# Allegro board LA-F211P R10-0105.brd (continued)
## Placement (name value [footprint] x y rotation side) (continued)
DT19  ESD8011MUT5G X3DFN2  [ESD108-B1-CSP0201_WLL-2-1-2]  11.31 82.89 90 bottom
DT20  ESD8011MUT5G X3DFN2  [ESD108-B1-CSP0201_WLL-2-1-2]  11.31 82.89 90 top
DT23  ESD8011MUT5G X3DFN2  [ESD108-B1-CSP0201_WLL-2-1-2]  11.31 84.07 90 bottom
DT24  ESD8011MUT5G X3DFN2  [ESD108-B1-CSP0201_WLL-2-1-2]  11.31 84.07 90 top
DT27  ESD8011MUT5G X3DFN2  [ESD108-B1-CSP0201_WLL-2-1-2]  11.31 85.49 270 bottom
DT28  ESD8011MUT5G X3DFN2  [ESD108-B1-CSP0201_WLL-2-1-2]  11.31 85.49 270 top
DT31  ESD8011MUT5G X3DFN2  [ESD108-B1-CSP0201_WLL-2-1-2]  11.31 86.25 90 bottom
DT32  ESD8011MUT5G X3DFN2  [ESD108-B1-CSP0201_WLL-2-1-2]  11.31 86.25 90 top
DT36  AZ4520-01F.R7G_DFN1610P2E2  [AZ4520-01FPR7G_DFN1610P2E2]  12.25 103.79 180 bottom
DT41  ESD8011MUT5G X3DFN2  [ESD108-B1-CSP0201_WLL-2-1-2]  11.31 95.29 270 bottom
DT42  ESD8011MUT5G X3DFN2  [ESD108-B1-CSP0201_WLL-2-1-2]  11.31 95.29 270 top
DT45  ESD8011MUT5G X3DFN2  [ESD108-B1-CSP0201_WLL-2-1-2]  11.31 95.95 90 bottom
DT46  ESD8011MUT5G X3DFN2  [ESD108-B1-CSP0201_WLL-2-1-2]  11.31 95.95 90 top
DT49  ESD8011MUT5G X3DFN2  [ESD108-B1-CSP0201_WLL-2-1-2]  11.31 97.37 270 bottom
DT50  ESD8011MUT5G X3DFN2  [ESD108-B1-CSP0201_WLL-2-1-2]  11.31 97.37 270 top
DT53  ESD8011MUT5G X3DFN2  [ESD108-B1-CSP0201_WLL-2-1-2]  11.31 98.41 270 bottom
DT54  ESD8011MUT5G X3DFN2  [ESD108-B1-CSP0201_WLL-2-1-2]  11.31 98.41 270 top
DT57  ESD8011MUT5G X3DFN2  [ESD108-B1-CSP0201_WLL-2-1-2]  11.31 99.07 90 bottom
DT58  ESD8011MUT5G X3DFN2  [ESD108-B1-CSP0201_WLL-2-1-2]  11.31 99.07 90 top
DT61  ESD8011MUT5G X3DFN2  [ESD108-B1-CSP0201_WLL-2-1-2]  11.31 100.11 90 bottom
DT62  ESD8011MUT5G X3DFN2  [ESD108-B1-CSP0201_WLL-2-1-2]  11.31 100.11 90 top
DT65  ESD8011MUT5G X3DFN2  [ESD108-B1-CSP0201_WLL-2-1-2]  11.31 101.53 270 bottom
DT66  ESD8011MUT5G X3DFN2  [ESD108-B1-CSP0201_WLL-2-1-2]  11.31 101.53 270 top
DT67  ESD8011MUT5G X3DFN2  [ESD108-B1-CSP0201_WLL-2-1-2]  11.31 102.19 90 bottom
DT68  ESD8011MUT5G X3DFN2  [ESD108-B1-CSP0201_WLL-2-1-2]  11.31 102.19 90 top
DV4  -  [BAT54CW_SOT323-3]  67.79 93.4 270 bottom
DV5  -  [BAT54CW_SOT323-3]  61.25 92.03 270 top
DV6  -  [BAT54CW_SOT323-3]  62.57 92.06 90 top
DV7  -  [TVNST52302AB0_SOT523-3]  146.36 104.95 90 top
DV9  -  [BAT54CW_SOT323-3]  56.23 16.15 0 top
DV10  RB751S40T1G_SOD523-2  [AZ5125-01HPR7G_SOD523-2]  64.22 17.87 180 top
DV11  RB751S40T1G_SOD523-2  [AZ5125-01HPR7G_SOD523-2]  55.85 67.02 90 bottom
DV12  RB751S40T1G_SOD523-2  [AZ5125-01HPR7G_SOD523-2]  54.71 67.02 90 bottom
DV13  RB751S40T1G_SOD523-2  [AZ5125-01HPR7G_SOD523-2]  66.36 27.7 0 top
DV14  RB751S40T1G_SOD523-2  [AZ5125-01HPR7G_SOD523-2]  67.66 84.46 270 top
DV15  RB751S40T1G_SOD523-2  [AZ5125-01HPR7G_SOD523-2]  61.7 19.07 0 top
DZ1  BAT54ATB_SOT-523-3  [BAT54ATB_SOT523-3]  42.24 25.99 90 top
DZ123  RB751S40T1G_SOD523-2  [AZ5125-01HPR7G_SOD523-2]  18.93 47.39 270 top
DZ124  RB751S40T1G_SOD523-2  [AZ5125-01HPR7G_SOD523-2]  20.35 47.39 270 top
DZ127  RB751S40T1G_SOD523-2  [AZ5125-01HPR7G_SOD523-2]  21.5 47.39 270 top
DZ128  RB751S40T1G_SOD523-2  [AZ5125-01HPR7G_SOD523-2]  22.93 44.55 180 top
F1  0438.500WR 0.5A 32V UL/CSA  [R_0603]  162.07 3.17 270 bottom
FD1  FIDUCAL  [FIDUCIAL_C40M80]  11.92 105.09 0 top
FD2  FIDUCIAL  [FIDUCIAL_C40M80]  140.62 2.88 0 top
FD3  FIDUCAL  [FIDUCIAL_C40M80]  16.11 2.74 180 bottom
FD4  FIDUCIAL  [FIDUCIAL_C40M80]  149.81 106.26 180 bottom
H1  H_2P3  [H_2P3-G]  7.5 106.72 0 top
H3  H_2P3  [H_2P3-G]  6.56 90.62 0 top
H4  H_3P3  [H_3P3-G]  151.26 75.53 0 top
H5  -  [H_3P3]  14.28 14.87 0 top
H6  H_2P3  [H_2P3-G]  7.5 74.52 0 top
H7  H_2P3  [H_2P3-G]  7.21 3.13 0 top
H9  -  [H_3P9N]  86.95 94.92 0 top
H10  -  [H_3P9N]  140.91 75.27 0 top
H16  H_2P3  [H_2P3-G]  151.77 110.95 0 top
H17  -  [H_6P0N]  9.26 12.45 0 top
H18  -  [H_3P9N]  66.51 71.47 0 top
H19  -  [H_3P9N]  103.71 48.02 0 top
H20  -  [H_1P3X1P8]  12.71 1.9 0 top
H26  -  [H_1P6]  12.71 108.85 0 top
H27  -  [H_1P2]  70.81 98.44 0 top
H28  -  [H_3P5]  152.77 31.77 0 top
H40  -  [EMIST_SUL-12A2M_1P]  27.01 99.49 270 bottom
H41  -  [EMIST_SUL-12A2M_1P]  39.66 107.62 180 bottom
H42  -  [EMIST_SUL-12A2M_1P]  54.86 107.62 180 bottom
H43  -  [EMIST_SUL-12A2M_1P]  67.43 104.73 270 bottom
H49  -  [H_1P0N]  72.98 84.6 0 top
H50  -  [H_1P0N]  130.6 54.48 0 top
H51  -  [H_2P7N]  107.89 18.07 0 top
H52  -  [H_2P7N]  107.89 7.07 0 top
JAPS1  ACES_50506-01841-P01  [ACES_50506-01841-P01_18P-NPM]  73.83 8.4 0 top
JCAM1  ACES_50506-02041-P01  [ACES_50506-02041-P01_20P]  144.16 107.05 270 bottom
JCCG1  -  [ACES_50521-01041-P01_10P]  62.36 21.52 180 bottom
JCR1  T-SOL_158-1000902614  [T-SOL_158-1000902614_23P-T]  15.25 61.85 270 top
JDEBUG1  ACES_50521-01041-P01  [ACES_50521-01041-P01_10P-NPM]  56.26 40.3 180 bottom
JDEG1  -  [ACES_50521-01041-P01_10P]  52.39 4.71 180 bottom
JDGPU1  ACES_50521-01041-P01_10P  [ACES_50521-01041-P01_10P-NPM]  72.77 7.62 180 bottom
JEDP1  STARC_115B40-000000-G4-R  [STARC_115B40-000000-G4-R_40P]  44.41 94.17 0 bottom
JESPI1  ACES_50521-01041-P01_10P  [ACES_50521-01041-P01_10P-NPM]  24.06 19.1 90 bottom
JFAN1  JXT_WB247H-006G10M  [JXT_WB247H-006G10M_6P-T]  143.19 36.42 270 bottom
JFP1  ACES_50521-0084N-P01  [ACES_50521-0084N-P01_8P]  155.91 6.14 180 bottom
JIO1  LLGCAX005  [UNIMI_LLGCAX005_182P-T]  114.06 19.9 180 bottom
JKB1  ACES_50696-0260M-P01  [ACES_50696-0260M-P01_26P]  37.92 7.86 180 bottom
JNGFF2  BELLW_80159-3221  [BELLW_80159-3221_67P]  97.81 5.62 90 bottom
JRTC1  ACES_50271-0020N-001  [ACES_50271-0020N-001_2P]  164.07 5.87 270 bottom
JSPI2  ACES_50521-01041-P01  [ACES_50521-01041-P01_10P]  81.85 7.62 180 bottom
JTAG2  @SHORT PADS~D  [SHORTPADS]  55.22 12.02 0 top
JUSBC1  JAE_DX07B024XJ1R1300~D  [JAE_DX07B024XJ1R1300_24P]  8.91 85.27 270 top
JUSBC2  JAE_DX07B024XJ1R1300~D  [JAE_DX07B024XJ1R1300_24P]  8.91 101.47 270 top
LED2  27-21-T3D-CP1Q2B16Y-3C_WHITE  [LED_LTW-270TLA_2P]  4.41 30.04 90 top
LED3  27-21-T3D-CP1Q2B16Y-3C_WHITE  [LED_LTW-270TLA_2P]  4.41 33.64 90 top
LED4  27-21-T3D-CP1Q2B16Y-3C_WHITE  [LED_LTW-270TLA_2P]  4.41 37.24 90 top
LED5  27-21-T3D-CP1Q2B16Y-3C_WHITE  [LED_LTW-270TLA_2P]  4.41 40.84 90 top
LED6  27-21-T3D-CP1Q2B16Y-3C_WHITE  [LED_LTW-270TLA_2P]  4.41 44.44 90 top
LED7  27-21-T3D-CP1Q2B16Y-3C_WHITE  [LED_LTW-270TLA_2P]  98.12 14.16 90 top
LED_PRI  HT-F196BP5_WHITE  [LED_HT-F196BP5_2P]  25.56 17.49 90 bottom
LED_RST  HT-F196BP5_WHITE  [LED_HT-F196BP5_2P]  28.92 19.89 90 bottom
LED_RUN  HT-F196BP5_WHITE  [LED_HT-F196BP5_2P]  27.66 19.88 90 bottom
LH1  BLM15GA750SN1D_2P  [MURAT_BLM15GA750SN1D_2P]  31.85 43.01 90 top
LH2  BLM15GA750SN1D_2P  [MURAT_BLM15GA750SN1D_2P]  28.54 41.23 180 top
LP1  2.2UH_MHCD252012A-2R2M-A8S_2A_20%  [CHILI_MHCD252012A-2R2M-A8S_2P]  22.32 65.76 90 bottom
LP2  2.2UH_MHCD252012A-2R2M-A8S_2A_20%  [CHILI_MHCD252012A-2R2M-A8S_2P]  29.13 98.89 0 bottom
LT1  0.60UH +-20% MND-04ABIR60M-XGL  [MAG_MND-04ABIR60M-XGL_2P]  33.3 89.58 180 bottom
LT2  LQM18PN1R0MFHD_2P  [CHILI_PBY160808T-300Y-N_2P]  29.94 85.22 90 top
LT4  DLM0NSN900HY2D_4P  [MURAT_DLM0NSN900HY2D_4P]  14.07 82.33 90 top
LT8  DLM0NSN900HY2D_4P  [MURAT_DLM0NSN900HY2D_4P]  13.37 97.32 90 top
LT10  DLM0NSN900HY2D_4P  [MURAT_DLM0NSN900HY2D_4P]  13.87 97.25 90 bottom
LT11  DLM0NSN900HY2D_4P  [MURAT_DLM0NSN900HY2D_4P]  14.19 82.82 180 bottom
LV4  DLM0NSN900HY2D_4P  [MURAT_DLM0NSN900HY2D_4P]  150.22 104.68 90 top
MD3  -  [TVNST52302AB0_SOT523-3]  131.42 5.42 0 top
ML1  DLM0NSN900HY2D_4P  [MURAT_DLM0NSN900HY2D_4P]  151.31 1.7 0 bottom
NOREF  -  []  70.81 98.44 90 top
NOREF#2  -  []  114.14 -2.84 0 top
NOREF#3  -  []  6.56 90.62 0 top
NOREF#4  -  []  151.26 75.53 0 top
NOREF#5  -  []  151.77 110.95 0 top
NOREF#6  -  []  62.18 -34.18 0 top
NOREF#7  -  []  147.14 20.72 0 top
NOREF#8  -  []  7.5 106.72 0 top
NOREF#9  -  []  127.63 6.04 0 top
NOREF#10  -  []  98.21 0.32 0 top
NOREF#11  -  []  80.68 2.04 0 top
NOREF#12  -  []  107.89 17.8 0 top
NOREF#13  -  []  7.21 3.13 90 top
NOREF#14  -  []  7.21 3.13 0 top
NOREF#15  -  []  3.56 107.32 0 top
NOREF#16  -  []  11.11 42.56 0 top
NOREF#17  -  []  14.28 14.87 0 top
NOREF#18  -  []  86.65 -13.32 270 top
NOREF#19  -  []  7.5 74.52 0 top
NOREF#20  -  []  107.89 7.07 0 top
NOREF#21  -  []  110.96 9.88 0 top
NOREF#22  -  []  29.8 157.9 0 top
NOREF#23  -  []  152.77 31.77 0 top
NOREF#24  -  []  119.19 25.29 0 top
NOREF#25  -  []  12.71 108.85 0 top
NOREF#26  -  []  39.16 24.74 180 bottom
NOREF#27  -  []  76.31 26.24 180 bottom
NOREF#28  -  []  60.99 22.75 180 bottom
PC100  0.022U_0402_25V7K  [C_0402]  19.07 75.52 0 top
PC101  2200P_0402_50V7K  [C_0402]  11.45 73.56 270 bottom
PC102  0.01U_0402_25V7K  [C_0402]  12.37 73.97 180 top
PC103  0.1U_0402_25V6  [C_0402]  12.37 73.08 180 top
PC104  100P_0201_50V8J  [C_0201]  11.82 74.4 180 bottom
PC105  2200P_0402_50V7K  [C_0402]  11.66 71.74 180 bottom
PC106  1000P_0201_50V7K  [C_0201]  14.79 73.54 180 top
PC107  100P_0201_50V8J  [C_0201]  18.87 70.64 270 bottom
PC108  0.1U_0402_25V6  [C_0402]  17.17 70.48 0 bottom
PC109  1U_0603_25V6K  [C_0603]  12.01 69.41 180 bottom
PC110  10U_0603_25V6M  [C_0603]  11.67 70.66 180 bottom
PC111  0.47U_0402_25V6K  [C_0402]  25.42 77.3 0 top
PC112  0.022U_0402_25V7K  [C_0402]  24.79 73.3 180 top
PC114  0.022U_0402_25V7K  [C_0402]  24.41 95.07 90 top
PC115  2200P_0402_50V7K  [C_0402]  16.13 100.48 270 bottom
PC116  0.01U_0402_25V7K  [C_0402]  17.01 100.48 270 bottom
PC117  0.1U_0402_25V6  [C_0402]  19.45 101.56 0 bottom
PC118  1000P_0201_50V7K  [C_0201]  19.66 94.74 270 bottom
PC119  1U_0603_25V6K  [C_0603]  18.13 96.92 180 bottom
PC120  2200P_0402_50V7K  [C_0402]  18.89 94.71 270 bottom
PC121  0.1U_0402_25V6  [C_0402]  17.24 94.65 270 bottom
PC122  100P_0201_50V8J  [C_0201]  19.49 102.32 0 bottom
PC123  10U_0603_25V6M  [C_0603]  18.13 95.71 180 bottom
PC124  0.47U_0402_25V6K  [C_0402]  18.83 98.68 0 top
PC125  0.022U_0402_25V7K  [C_0402]  24.44 93.66 270 top
PC127  1000P_0402_25V8J  [C_0402]  40.08 104.3 0 top
PC128  100P_0402_50V8J  [C_0402]  27.11 96.17 270 top
PC129  100P_0402_50V8J  [C_0402]  34.13 103 90 top
PC132  100P_0201_50V8J  [C_0201]  136.97 6.69 0 bottom
PC133  0.01UF_0402_25V7K  [C_0402]  135.56 7.58 180 bottom
PC134  1000P_0201_50V7K  [C_0201]  135.63 6.69 0 bottom
PC135  100P_0201_50V8J  [C_0201]  128.62 20.85 90 bottom
PC136  2.2U_0402_25V6M  [C_0402]  29.13 106.11 90 top
PC137  0.1U_0402_10V7K  [C_0402]  29.18 103.27 180 top
PC138  2.2U_0402_25V6M  [C_0402]  32.95 94.35 270 top
PC139  0.1U_0402_10V7K  [C_0402]  34.73 93.44 90 top
PC140  10U_0402_6.3V6M  [C_0402]  34.13 105.76 270 top
PC141  10U_0402_6.3V6M  [C_0402]  27.99 94.33 180 top
PC142  100P_0201_50V8J  [C_0201]  20.23 94.74 270 bottom
PC143  0.1U_0402_10V7K  [C_0402]  48.75 107.17 270 top
PC144  0.1U_0402_10V7K  [C_0402]  37.07 101.34 180 top
PC145  0.1U_0402_10V7K  [C_0402]  41.59 100.12 270 top
PC146  0.1U_0402_10V7K  [C_0402]  48.27 104.44 270 top
PC330  1U_0603_25V6K  [C_0603]  46.9 64.22 180 bottom
PC331  1U_0402_10V6K  [C_0402]  45.54 70.28 180 bottom
PC332  1U_0402_10V6K  [C_0402]  44.65 69.35 0 bottom
PC341  0.01U_0402_16V7K  [C_0402]  48.88 64.1 0 top
PC342  0.1U_0402_25V6  [C_0402]  52.68 70.68 90 top
PC500  0.1U_0402_25V6  [C_0402]  148.48 4.39 90 bottom
PC501  0.1U_0402_25V6  [C_0402]  159.48 17.71 0 top
PC502  2200P_0402_50V7K  [C_0402]  157.58 9.8 180 top
PC503  10U_0603_25V6M  [C_0603]  147.33 7.32 90 bottom
PC504  10U_0603_25V6M  [C_0603]  160.44 14.5 0 bottom
PC505  10U_0603_25V6M  [C_0603]  155.93 11.83 270 bottom
PC506  10U_0603_25V6M  [C_0603]  148.96 9.82 180 bottom
PC507  10U_0603_25V6M  [C_0603]  157.2 11.83 270 bottom
PC508  10U_0603_25V6M  [C_0603]  154.66 11.83 270 bottom
PC509  10U_0603_25V6M  [C_0603]  160.44 15.77 0 bottom
PC510  4.7U_0402_6.3V6M  [C_0402]  158.85 6.18 90 top
PC511  0.1U_0201_25V6K  [C_0201]  161.64 2.28 90 top
PC512  1U_0402_25V6K  [C_0402]  155.39 6.46 180 top
PC513  1U_0402_25V6K  [C_0402]  155.39 9.8 180 top
PC514  10U_0603_25V6M  [C_0603]  133.51 23.64 270 bottom
PC515  10U_0603_25V6M  [C_0603]  134.72 23.64 270 bottom
PC516  10U_0603_25V6M  [C_0603]  133.38 21.16 0 bottom
PC517  10U_0603_25V6M  [C_0603]  129.96 28.21 270 bottom
PC518  10U_0603_25V6M  [C_0603]  142.53 7.96 90 bottom
PC519  10U_0603_25V6M  [C_0603]  137.13 23.64 270 bottom
PC520  10U_0603_25V6M  [C_0603]  135.92 23.64 270 bottom
PC521  10U_0603_25V6M  [C_0603]  143.8 7.96 90 bottom
PC522  10U_0603_25V6M  [C_0603]  135.04 12.46 90 bottom
PC523  0.1U_0402_25V6  [C_0402]  135.56 11.51 180 bottom
PC524  2200P_0402_50V7K  [C_0402]  135.56 10.56 180 bottom
PC525  0.22U_0603_25V7K  [C_0603]  157.77 9.31 0 bottom
PC526  1U_0603_25V6K  [C_0603]  161.16 7.65 0 bottom
PC527  1U_0603_25V6K  [C_0603]  161.71 6.55 270 bottom
PC528  1U_0402_6.3V6K  [C_0402]  159.81 10.51 90 top
PC529  1U_0402_6.3V6K  [C_0402]  161.18 3.64 0 top
PC530  0.22U_0603_25V7K  [C_0603]  163.43 11.45 90 bottom
PC531  10U_0603_25V6M  [C_0603]  142.78 6.88 0 bottom
PC532  10U_0603_25V6M  [C_0603]  142.78 5.67 0 bottom
PC533  4700P_0402_25V7K  [C_0402]  165.59 10.43 0 top
PC534  2200P_0402_50V7K  [C_0402]  135.56 8.53 180 bottom
PC535  0.1U_0402_25V6  [C_0402]  161.59 12.44 180 top
PC536  680P_0402_50V7K  [C_0402]  158.59 17.79 90 top
PC537  680P_0402_50V7K  [C_0402]  137.08 18.12 180 top
PC538  1U_0402_25V6K  [C_0402]  162.49 13.85 270 top
PC539  1U_0402_6.3V6K  [C_0402]  162.9 11.87 0 top
PC540  0.22U_0402_25V6K  [C_0402]  164.64 11.64 0 top
PC541  560P_0402_50V7K  [C_0402]  169.06 5.96 0 top
PC542  0.01U_0402_16V7K  [C_0402]  169.05 6.89 0 top
PC543  0.1U_0201_25V6K  [C_0201]  170.74 6.99 0 top
PC544  0.1U_0402_25V6  [C_0402]  167.76 8.55 90 top
PC545  100U_D_20VM_R55M  [C_D]  132.69 26.5 0 bottom
PC546  10P_0402_50V8J  [C_0402]  167.22 3.9 0 top
PC547  0.1U_0402_25V6  [C_0402]  30.68 3.43 90 top
PC548  10U_0603_25V6M  [C_0603]  159.74 11.83 270 bottom
PC549  10U_0603_25V6M  [C_0603]  158.47 11.83 270 bottom
PC550  10U_0603_25V6M  [C_0603]  160.44 13.23 0 bottom
PC600  0.22U_0402_16V7K  [C_0402]  15.03 25.36 180 bottom
PC601  0.1U_0402_25V6  [C_0402]  10.84 20.78 180 top
PC602  2200P_0402_50V7K  [C_0402]  10.84 20.78 180 bottom
PC603  10U_0603_25V6M  [C_0603]  10.77 19.7 180 bottom
PC604  10U_0603_25V6M  [C_0603]  10.7 19.64 180 top
PC605  4.7U_0402_6.3V6M  [C_0402]  7.16 25.63 270 bottom
PC606  47U_0603_6.3V6M  [C_0603]  15.47 30.88 90 bottom
PC607  47U_0603_6.3V6M  [C_0603]  16.74 30.88 90 bottom
PC608  47U_0603_6.3V6M  [C_0603]  14.32 28.72 270 bottom
PC609  47U_0603_6.3V6M  [C_0603]  14.2 30.88 90 bottom
PC610  1U_0402_10V6K  [C_0402]  13.18 23.78 270 bottom
PC611  680P_0402_50V7K  [C_0402]  12.93 23.83 90 top
PC612  0.22U_0402_16V7K  [C_0402]  61.96 82.67 90 bottom
PC613  0.1U_0402_25V6  [C_0402]  56.7 77.85 180 bottom
PC614  2200P_0402_50V7K  [C_0402]  58.77 77.81 0 bottom
PC615  10U_0603_25V6M  [C_0603]  56.31 75.41 180 bottom
PC616  10U_0603_25V6M  [C_0603]  56.29 76.73 180 bottom
PC617  4.7U_0402_6.3V6M  [C_0402]  52.81 81.32 0 bottom
PC618  47U_0603_6.3V6M  [C_0603]  54.95 90.34 90 bottom
PC619  47U_0603_6.3V6M  [C_0603]  53.61 89.39 90 bottom
PC620  47U_0603_6.3V6M  [C_0603]  52.46 90.61 180 bottom
PC621  47U_0603_6.3V6M  [C_0603]  52.47 89.36 180 bottom
PC622  1U_0402_10V6K  [C_0402]  59.72 81.21 270 bottom
PC623  680P_0402_50V7K  [C_0402]  53.5 80.61 270 top
PC624  0.22U_0402_16V7K  [C_0402]  123.71 28.34 180 bottom
PC625  0.1U_0402_25V6  [C_0402]  130.02 24.96 90 bottom
PC626  2200P_0402_50V7K  [C_0402]  129.13 24.96 90 bottom
PC627  10U_0603_25V6M  [C_0603]  128.18 23.89 270 bottom
PC628  10U_0603_25V6M  [C_0603]  128.05 24.91 90 bottom
PC629  4.7U_0402_6.3V6M  [C_0402]  123.53 21 0 bottom
PC630  47U_0603_6.3V6M  [C_0603]  109.83 26.82 90 bottom
PC631  47U_0603_6.3V6M  [C_0603]  111.03 26.82 90 bottom
PC632  47U_0603_6.3V6M  [C_0603]  113.45 26.82 90 bottom
PC633  47U_0603_6.3V6M  [C_0603]  112.24 26.82 90 bottom
PC634  1U_0402_10V6K  [C_0402]  124.55 26.85 0 bottom
PC635  680P_0402_50V7K  [C_0402]  125.21 25.43 0 top
PC636  0.22U_0402_16V7K  [C_0402]  67.66 106.7 270 top
PC637  0.1U_0402_25V6  [C_0402]  59.52 103.92 270 bottom
PC638  2200P_0402_50V7K  [C_0402]  59.52 103.91 270 top
PC639  10U_0603_25V6M  [C_0603]  60.6 103.83 270 bottom
PC640  10U_0603_25V6M  [C_0603]  60.59 103.84 270 top
PC641  4.7U_0402_6.3V6M  [C_0402]  66.07 100.16 180 top
PC642  47U_0603_6.3V6M  [C_0603]  74.68 105.54 90 top
PC643  47U_0603_6.3V6M  [C_0603]  72.11 104.86 90 top
PC644  47U_0603_6.3V6M  [C_0603]  73.38 105.49 90 top
PC645  47U_0603_6.3V6M  [C_0603]  75.98 105.56 90 top
PC646  1U_0402_10V6K  [C_0402]  65.44 106.06 180 top
PC647  680P_0402_50V7K  [C_0402]  68.17 101.75 0 top
PC700  680P_0402_50V7K  [C_0402]  11.4 50.68 90 top
PC701  2200P_0402_50V7K  [C_0402]  6.58 50.54 180 bottom
PC702  0.1U_0402_25V6  [C_0402]  6.58 51.47 180 bottom
PC703  10U_0603_25V6M  [C_0603]  8.23 54.87 0 bottom
PC704  10U_0603_25V6M  [C_0603]  8.21 53.6 0 bottom
PC705  0.1U_0201_10V6K  [C_0201]  6.28 48.06 0 bottom
PC706  330P_0402_50V7K  [C_0402]  14.33 51.31 180 bottom
PC707  22U_0603_6.3V6M  [C_0603]  10.32 37.55 180 bottom
PC708  22U_0603_6.3V6M  [C_0603]  10.32 35.13 180 bottom
PC709  22U_0603_6.3V6M  [C_0603]  10.32 33.86 180 bottom
PC710  22U_0603_6.3V6M  [C_0603]  10.32 36.34 180 bottom
PC711  2.2U_0402_6.3V6M  [C_0402]  13.12 48.47 0 bottom
PC712  0.1U_0402_25V6  [C_0402]  12.37 55.01 180 bottom
PC713  1U_0402_6.3V6K  [C_0402]  13.13 49.43 0 bottom
PC800  0.22U_0402_16V7K  [C_0402]  85.12 98.81 144.6 bottom
PC801  680P_0402_50V7K  [C_0402]  78.1 98.52 180 top
PC802  220P_0402_50V8J  [C_0402]  81.84 97.48 270 top
PC803  47U_0603_6.3V6M  [C_0603]  86.84 102.63 90 bottom
PC804  47U_0603_6.3V6M  [C_0603]  88.11 102.63 90 bottom
PC805  47U_0603_6.3V6M  [C_0603]  88.1 100.21 270 bottom
PC806  47U_0603_6.3V6M  [C_0603]  86.88 100.21 270 bottom
PC807  10U_0603_25V6M  [C_0603]  79.69 91.78 180 bottom
PC808  0.1U_0402_25V6  [C_0402]  80.63 91.97 180 top
PC809  2200P_0402_25V7K  [C_0402]  80.95 93.43 180 top
PC810  10U_0402_6.3V6M  [C_0402]  75.55 94.13 180 bottom
PC811  10U_0402_6.3V6M  [C_0402]  76.49 95.89 90 bottom
PC812  0.22U_0402_10V6K  [C_0402]  76.37 95.01 180 bottom
PC813  0.1U_0402_10V7K  [C_0402]  82.2 92.58 0 bottom
PC814  1U_0402_10V6K  [C_0402]  76.43 92.33 90 bottom
PC815  0.1U_0402_10V7K  [C_0402]  82.2 93.47 0 bottom
PC816  47U_0603_6.3V6M  [C_0603]  85.89 101.12 235 bottom
PC817  47U_0603_6.3V6M  [C_0603]  85.63 104.54 90 bottom
PC900  0.1U_0402_16V7K  [C_0402]  17.37 24.83 90 top
PC901  22U_0603_6.3V6M  [C_0603]  20.55 21.67 90 top
PC902  68P_0402_50V8J  [C_0402]  19.29 25.74 180 top
PC903  22U_0603_6.3V6M  [C_0603]  22.89 25.23 180 top
PC904  22U_0603_6.3V6M  [C_0603]  22.89 26.43 180 top
PC905  680P_0402_50V7K  [C_0402]  21.7 24.02 180 top
PC1000  2200P_0402_50V7K  [C_0402]  95.55 26.22 270 top
PC1001  0.1U_0402_25V6  [C_0402]  96.47 26.24 270 top
PC1002  0.1U_0201_10V6K  [C_0201]  100.36 30.26 0 top
PC1003  10U_0805_25V6K  [C_0805]  97.81 26.69 270 top
PC1004  680P_0402_50V7K  [C_0402]  98.51 32.07 90 top
PC1005  10U_0805_25V6K  [C_0805]  99.74 26.71 270 top
PC1006  22U_0603_6.3V6M  [C_0603]  100.81 41.93 180 top
PC1007  22U_0603_6.3V6M  [C_0603]  100.81 43.14 180 top
PC1008  22U_0603_6.3V6M  [C_0603]  100.81 40.72 180 top
PC1009  22U_0603_6.3V6M  [C_0603]  99.35 44.47 180 top
PC1010  2.2U_0402_6.3V6M  [C_0402]  104.44 30.31 0 top
PC1011  0.47U_0402_25V6K  [C_0402]  106.22 24.47 180 top
PC1012  330P_0402_50V7K  [C_0402]  107.11 26.56 180 top
PC1013  1U_0402_6.3V6K  [C_0402]  106.19 29.23 0 top
PC1014  22U_0603_6.3V6M  [C_0603]  100.81 39.48 180 top
PC1100  0.01U_0402_50V7K  [C_0402]  137.07 36.92 270 top
PC1101  1U_0603_10V6K  [C_0603]  144.87 44.91 90 top
PC1102  4.7U_0603_10V6K  [C_0603]  136.31 40.98 180 top
PC1103  0.1U_0402_25V6  [C_0402]  137.07 43.97 270 top
PC1104  0.1U_0402_25V6  [C_0402]  140.94 50.17 90 top
PC1105  1U_0402_10V6K  [C_0402]  135.15 35.96 0 top
PC1106  0.01U_0402_16V7K  [C_0402]  137.33 31.39 180 top
PC1107  0.01U_0402_16V7K  [C_0402]  146.39 33.48 0 top
PC1108  470P_0402_50V8J  [C_0402]  148.38 40.6 180 top
PC1109  330P_0402_50V8J  [C_0402]  148.38 41.67 180 top
PC1110  68P_0402_50V8J  [C_0402]  148.38 42.75 180 top
PC1111  1U_0603_10V6K  [C_0603]  136.31 39.71 180 top
PC1112  0.01U_0402_16V7K  [C_0402]  147.47 36.85 0 top
PC1200  100U_D_20VM_R55M  [C_D]  137.49 37.88 90 bottom
PC1201  10U_0603_25V6M  [C_0603]  115.36 32.38 0 bottom
PC1202  10U_0603_25V6M  [C_0603]  113.72 32.51 270 bottom
PC1203  1U_0402_25V6K  [C_0402]  114.64 37.55 0 top
PC1204  0.1U_0402_25V7K  [C_0402]  114.64 35.77 0 top
PC1205  2200P_0402_50V7K  [C_0402]  114.64 36.66 0 top
PC1206  1.5P_0402_50V8  [C_0402]  114.64 34.88 0 top
PC1207  1U_0402_6.3V7K  [C_0402]  112.67 37.33 270 bottom
PC1208  0.22U_0402_16V7K  [C_0402]  112.63 38.22 90 bottom
PC1209  680P_0603_50V7K  [C_0603]  116.94 40.98 270 top
PC1210  1U_0402_6.3V7K  [C_0402]  119.86 37.08 270 bottom
PC1211  10U_0603_25V6M  [C_0603]  122.52 32.11 0 bottom
PC1212  10U_0603_25V6M  [C_0603]  118.93 32.56 270 bottom
PC1213  1U_0402_25V6K  [C_0402]  122.32 37.17 0 top
PC1214  0.1U_0402_25V7K  [C_0402]  122.32 34.05 0 top
PC1215  2200P_0402_50V7K  [C_0402]  122.32 34.94 0 top
PC1216  0.22U_0402_16V7K  [C_0402]  120.2 38.21 90 bottom
PC1217  680P_0603_50V7K  [C_0603]  124.67 41.36 270 top
PC1218  1U_0402_25V6K  [C_0402]  129.56 38.18 0 top
PC1219  0.1U_0402_25V7K  [C_0402]  129.56 36.34 0 top
PC1220  1U_0402_6.3V7K  [C_0402]  127.05 38.45 270 bottom
PC1221  10U_0603_25V6M  [C_0603]  127.5 32.54 270 bottom
PC1222  10U_0603_25V6M  [C_0603]  128.71 32.64 270 bottom
PC1223  2200P_0402_50V7K  [C_0402]  129.56 37.23 0 top
PC1224  0.22U_0402_16V7K  [C_0402]  127.86 39.69 90 bottom
PC1225  680P_0603_50V7K  [C_0603]  131.4 42.28 270 top
PC1226  10U_0603_25V6M  [C_0603]  120.18 32.53 270 bottom
PC1227  10U_0603_25V6M  [C_0603]  129.97 33.16 0 bottom
PC1228  10U_0603_25V6M  [C_0603]  112.49 32.53 270 bottom
PC1300  10U_0603_25V6M  [C_0603]  150.53 61.8 180 bottom
PC1301  10U_0603_25V6M  [C_0603]  144.87 65.49 90 top
PC1302  10U_0603_25V6M  [C_0603]  147.8 49.04 270 bottom
PC1303  1U_0402_25V6K  [C_0402]  147.1 55.63 90 top
PC1304  0.1U_0402_25V6  [C_0402]  148.05 55.63 90 top
PC1305  2200P_0402_50V7K  [C_0402]  149.01 55.63 90 top
PC1306  2.2U_0402_25V6M  [C_0402]  146.77 53.04 0 bottom
PC1307  0.22U_0402_16V7K  [C_0402]  146.15 51.14 180 bottom
PC1308  680P_0603_50V7K  [C_0603]  143.38 61.08 0 top
PC1309  2.2U_0402_25V6M  [C_0402]  147.47 62.88 0 bottom
PC1310  10U_0603_25V6M  [C_0603]  151.06 55.85 90 bottom
PC1311  10U_0603_25V6M  [C_0603]  144.85 55.25 90 top
PC1312  10U_0603_25V6M  [C_0603]  151.61 65.42 90 bottom
PC1313  1U_0402_25V6K  [C_0402]  147.42 65.79 90 top
PC1314  0.1U_0402_25V6  [C_0402]  149.32 65.79 90 top
PC1315  2200P_0402_50V7K  [C_0402]  148.37 65.79 90 top
PC1316  0.22U_0402_16V7K  [C_0402]  146.61 61.92 180 bottom
PC1317  680P_0603_50V7K  [C_0603]  142.4 67.01 0 top
PC1318  1U_0402_25V6K  [C_0402]  107.97 38.31 0 top
PC1319  10U_0603_25V6M  [C_0603]  108.7 33.97 0 top
PC1320  10U_0603_25V6M  [C_0603]  107.93 35.48 0 top
PC1321  10U_0603_25V6M  [C_0603]  108.63 33.43 0 bottom
PC1322  0.1U_0402_25V7K  [C_0402]  107.97 37.42 0 top
PC1323  2200P_0402_50V7K  [C_0402]  107.97 36.53 0 top
PC1324  1U_0402_6.3V7K  [C_0402]  105.79 38.31 270 bottom
PC1325  0.22U_0402_16V7K  [C_0402]  105.79 39.27 90 bottom
PC1326  680P_0603_50V7K  [C_0603]  110.27 41.48 270 top
PC1379  22U_0603_6.3VAM  [C_0603]  110.91 48.91 0 bottom
PC1380  22U_0603_6.3VAM  [C_0603]  110.91 47.71 0 bottom
PC1381  22U_0603_6.3V6M  [C_0603]  110.14 44.47 180 top
PC1382  22U_0603_6.3V6M  [C_0603]  113.06 50.74 180 top
PC1383  22U_0603_6.3V6M  [C_0603]  113.83 62.69 180 top
PC1384  22U_0603_6.3V6M  [C_0603]  113.83 66.88 180 top
PC1385  22U_0603_6.3V6M  [C_0603]  113.83 65.49 180 top
PC1386  22U_0603_6.3V6M  [C_0603]  113.83 68.28 180 top
PC1387  22U_0603_6.3V6M  [C_0603]  113.83 64.09 180 top
PC1388  22U_0603_6.3V6M  [C_0603]  114.84 66.88 0 top
PC1389  22U_0603_6.3V6M  [C_0603]  114.84 65.49 0 top
PC1391  22U_0603_6.3V6M  [C_0603]  114.84 62.69 0 top
PC1392  22U_0603_6.3V6M  [C_0603]  114.84 64.09 0 top
PC1393  22U_0603_6.3VAM  [C_0603]  109.32 47.71 180 bottom
PC1400  560U_D2_2VM_R4.5M  [C_D2]  119.1 50.6 0 bottom
PC1401  220U_D7_2VM_R6M  [C_EEFSS0D221R]  122.95 47.77 0 top
PC1402  22U_0603_6.3VAM  [C_0603]  114.92 48.88 180 bottom
PC1403  22U_0603_6.3V6M  [C_0603]  118.65 67.9 180 top
PC1404  22U_0603_6.3V6M  [C_0603]  124.24 50.76 0 top
PC1405  22U_0603_6.3V6M  [C_0603]  126.65 50.76 0 top
PC1406  22U_0603_6.3VAM  [C_0603]  135.28 48.32 0 bottom
PC1407  22U_0603_6.3V6M  [C_0603]  130.46 50.76 180 top
PC1408  22U_0603_6.3V6M  [C_0603]  119.8 66.5 0 top
PC1409  22U_0603_6.3V6M  [C_0603]  118.65 66.5 180 top
PC1410  22U_0603_6.3V6M  [C_0603]  119.8 67.9 0 top
PC1411  22U_0603_6.3V6M  [C_0603]  131.54 50.31 270 top
PC1412  22U_0603_6.3V6M  [C_0603]  122.34 66.5 0 top
PC1413  22U_0603_6.3VAM  [C_0603]  134.13 49.64 0 bottom
PC1414  10U_0402_6.3V6M  [C_0402]  119.02 74.5 0 top
PC1415  10U_0402_6.3V6M  [C_0402]  114.35 75.52 180 top
PC1416  10U_0402_6.3V6M  [C_0402]  121.97 62.57 180 top
PC1417  10U_0402_6.3V6M  [C_0402]  118.16 62.57 180 top
PC1418  10U_0402_6.3V6M  [C_0402]  118.16 63.71 180 top
PC1419  10U_0402_6.3V6M  [C_0402]  119.15 62.57 0 top
PC1420  10U_0402_6.3V6M  [C_0402]  118.03 75.52 180 top
PC1421  10U_0402_6.3V6M  [C_0402]  115.34 75.52 0 top
PC1422  10U_0402_6.3V6M  [C_0402]  118.03 74.5 180 top
PC1423  10U_0402_6.3V6M  [C_0402]  122.96 62.57 0 top
PC1424  10U_0402_6.3V6M  [C_0402]  115.34 74.5 0 top
PC1425  10U_0402_6.3V6M  [C_0402]  121.97 63.71 180 top
PC1426  10U_0402_6.3V6M  [C_0402]  122.96 63.71 0 top
PC1427  10U_0402_6.3V6M  [C_0402]  119.15 63.71 0 top
PC1428  10U_0402_6.3V6M  [C_0402]  119.02 75.52 0 top
PC1430  22U_0603_6.3V6M  [C_0603]  117.13 50.76 0 top
PC1431  22U_0603_6.3V6M  [C_0603]  124.62 61.17 0 top
PC1432  22U_0603_6.3VAM  [C_0603]  115.03 50.18 90 bottom
PC1433  22U_0603_6.3V6M  [C_0603]  120.88 50.76 180 top
PC1434  22U_0603_6.3V6M  [C_0603]  122.34 65.11 0 top
PC1435  22U_0603_6.3V6M  [C_0603]  119.8 65.11 0 top
PC1436  22U_0603_6.3V6M  [C_0603]  118.65 65.11 180 top
PC1437  22U_0603_6.3VAM  [C_0603]  116.3 50.18 90 bottom
PC1442  1U_0201_6.3V6M  [C_0201]  120.91 61.68 180 top
PC1443  1U_0201_6.3V6M  [C_0201]  115.71 77.04 180 top
PC1444  1U_0201_6.3V6M  [C_0201]  117.93 61.68 180 top
PC1445  1U_0201_6.3V6M  [C_0201]  124.9 62.19 0 top
PC1446  1U_0201_6.3V6M  [C_0201]  116.52 76.41 0 top
PC1447  1U_0201_6.3V6M  [C_0201]  117.93 60.92 180 top
PC1448  1U_0201_6.3V6M  [C_0201]  118.75 77.04 180 top
PC1449  1U_0201_6.3V6M  [C_0201]  119.06 61.68 0 top
PC1450  1U_0201_6.3V6M  [C_0201]  114.31 77.04 180 top
PC1451  1U_0201_6.3V6M  [C_0201]  114.31 76.41 180 top
PC1457  1U_0201_6.3V6M  [C_0201]  124.9 62.82 0 top
PC1458  1U_0201_6.3V6M  [C_0201]  118.75 76.41 180 top
PC1459  1U_0201_6.3V6M  [C_0201]  119.06 60.92 0 top
PC1460  1U_0201_6.3V6M  [C_0201]  120.91 60.92 180 top
PC1461  1U_0201_6.3V6M  [C_0201]  122.18 60.92 180 top
PC1462  1U_0201_6.3V6M  [C_0201]  122.18 61.68 180 top
PC1463  1U_0201_6.3V6M  [C_0201]  115.71 76.41 180 top
PC1464  1U_0201_6.3V6M  [C_0201]  123.12 61.68 0 top
PC1465  1U_0201_6.3V6M  [C_0201]  116.52 77.04 0 top
PC1466  1U_0201_6.3V6M  [C_0201]  123.12 60.92 0 top
PC1467  0.1U_0402_10V7K  [C_0402]  133.58 46.95 90 top
PC1468  0.1U_0402_10V7K  [C_0402]  131.42 46.95 90 top
PC1469  100P_0402_50V8J  [C_0402]  132.43 46.95 90 top
PC1470  100P_0402_50V8J  [C_0402]  133.07 45.93 270 top
PC1499  220U_D7_2VM_R6M  [C_EEFSS0D221R]  119.25 47.73 180 top
PC1500  0.1U_0402_16V7K  [C_0402]  68.55 83.06 90 bottom
PC1501  22U_0603_6.3V6M  [C_0603]  69.19 77.65 180 bottom
PC1502  68P_0402_50V8J  [C_0402]  65.39 80.85 0 bottom
PC1503  22U_0603_6.3V6M  [C_0603]  64.22 78.69 0 bottom
PC1504  22U_0603_6.3V6M  [C_0603]  67.41 77.62 90 top
PC1505  680P_0402_50V7K  [C_0402]  69.44 76.5 180 bottom
PC1800  4.7U_0603_6.3V  [C_0603]  51.85 32.85 270 top
PC1801  0.01U_0603_50V7K  [C_0603]  53.15 28.85 90 top
PC1802  0.1U_0402_16V7K  [C_0402]  49.3 32.2 0 top
PC1803  0.01U_0402_16V  [C_0402]  63.85 36.52 180 top
PC1804  0.1U_0603_16V  [C_0603]  49.62 36.79 0 top
PC1805  0.033U_0402_16V7K  [C_0402]  62.05 35.54 90 top
PC1806  0.033U_0402_16V7K  [C_0402]  62.77 39.19 90 top
PC1807  330P_0402_25V  [C_0402]  52.68 44.93 270 top
PC1808  2200P_0402_25V  [C_0402]  54.64 44.1 270 top
PC1809  47P_0402_50V8J  [C_0402]  53.74 42.31 0 top
PC1810  0.033U_0402_16V7K  [C_0402]  61.88 37.41 90 top
PC1811  0.033U_0402_16V7K  [C_0402]  60.6 41.04 0 top
PC1812  1000P_0402_25V  [C_0402]  52.55 40.48 90 top
PC1813  2200P_0603_50V7K  [C_0603]  50.45 45.17 270 top
PC1814  2200P_0603_50V7K  [C_0603]  49.06 45.17 270 top
PC1815  1500P_0402_50V7K  [C_0402]  57.69 43.66 270 top
PC1816  680P_0402_50V7K  [C_0402]  55.91 44.52 90 top
PC1817  1000P_0402_25V  [C_0402]  59.48 41.87 180 top
PC1818  4700P_0402_25V7K  [C_0402]  55.77 42.75 0 top
PC1819  1000P_0402_25V  [C_0402]  58.82 40.98 0 top
PC1820  330P_0402_25V  [C_0402]  55.69 28.77 90 top
PC1821  2200P_0402_25V  [C_0402]  56.28 27.91 0 top
PC1822  47P_0402_50V8J  [C_0402]  56.41 26.96 0 top
PC1823  0.01U_0402_16V7K  [C_0402]  61.68 30.18 0 top
PC1824  1000P_0402_25V  [C_0402]  61.1 31.96 270 top
PC1825  1000P_0402_25V  [C_0402]  54.21 31.46 270 top
PC1826  1500P_0402_50V7K  [C_0402]  60.85 29.23 0 top
PC1827  680P_0402_50V7K  [C_0402]  60.85 28.34 0 top
PC1828  1000P_0402_25V  [C_0402]  58.26 29.47 90 top
PC1829  2200P_0402_25V  [C_0402]  58.33 27.59 270 top
PC1900  1U_0402_25V6K  [C_0402]  69.08 34.63 90 top
PC1901  1000P_0402_50V7K  [C_0402]  70.94 34.61 90 top
PC1902  0.1U_0402_25V7K  [C_0402]  67.22 35.58 90 bottom
PC1903  2200P_0402_50V7K  [C_0402]  68.12 35.57 90 top
PC1904  10U_0603_25V6M  [C_0603]  66.07 35.67 90 bottom
PC1905  10U_0603_25V6M  [C_0603]  66.07 35.67 90 top
PC1906  1U_0603_25V7K  [C_0603]  88.78 32.59 270 bottom
PC1907  0.22U_0603_25V7K  [C_0603]  85.94 32.56 270 bottom
PC1908  2.2U_0603_10V7K  [C_0603]  91.27 32.63 270 bottom
PC1909  2200P_0402_50V7K  [C_0402]  87.6 39.45 90 top
PC1910  1U_0402_25V6K  [C_0402]  77.71 34.6 90 top
PC1911  1000P_0402_50V7K  [C_0402]  76.74 35.32 90 top
PC1912  0.1U_0402_25V7K  [C_0402]  67.2 35.58 90 top
PC1913  2200P_0402_50V7K  [C_0402]  75.84 35.29 90 top
PC1914  10U_0603_25V6M  [C_0603]  74.77 35.36 90 bottom
PC1915  10U_0603_25V6M  [C_0603]  74.77 35.36 90 top
PC1916  1U_0603_25V7K  [C_0603]  71.46 32.61 270 bottom
PC1917  0.22U_0603_25V7K  [C_0603]  68.68 32.54 270 bottom
PC1918  2.2U_0603_10V7K  [C_0603]  73.96 32.58 270 bottom
PC1919  2200P_0402_50V7K  [C_0402]  70.58 39.53 90 top
PC1920  100U_D_20VM_R55M  [C_D]  101.06 26.43 0 bottom
PC1921  0.1U_0402_25V6  [C_0402]  79.68 34.65 90 top
PC1922  0.1U_0402_25V6  [C_0402]  75.84 35.29 90 bottom
PC2000  1U_0402_25V6K  [C_0402]  70.05 34.61 90 top
PC2001  1000P_0402_50V7K  [C_0402]  84.57 35.27 90 top
PC2002  0.1U_0402_25V7K  [C_0402]  84.57 35.29 90 bottom
PC2003  2200P_0402_50V7K  [C_0402]  85.53 35.29 90 top
PC2004  10U_0603_25V6M  [C_0603]  83.46 35.34 90 bottom
PC2005  10U_0603_25V6M  [C_0603]  83.46 35.34 90 top
PC2006  1U_0603_25V7K  [C_0603]  80.03 32.57 270 bottom
PC2007  0.22U_0603_25V7K  [C_0603]  77.31 32.56 270 bottom
PC2008  2.2U_0603_10V7K  [C_0603]  82.52 32.61 270 bottom
PC2009  2200P_0402_50V7K  [C_0402]  77.82 39.76 90 top
PC2010  10U_0603_25V6M  [C_0603]  92.3 35.3 90 bottom
PC2011  2200P_0402_50V7K  [C_0402]  93.4 35.25 90 top
PC2012  2.2U_0603_10V7K  [C_0603]  99.79 32.49 270 bottom
PC2013  1U_0402_25V6K  [C_0402]  78.69 34.63 90 top
PC2014  1000P_0402_50V7K  [C_0402]  95.34 35.26 0 top
PC2015  1U_0603_25V7K  [C_0603]  97.32 32.49 270 bottom
PC2016  0.1U_0402_25V7K  [C_0402]  86.48 35.32 0 top
PC2017  10U_0603_25V6M  [C_0603]  92.31 35.31 90 top
PC2018  0.22U_0603_25V7K  [C_0603]  94.59 32.52 270 bottom
PC2019  2200P_0402_50V7K  [C_0402]  96.36 39.36 90 top
PC2020  0.1U_0402_25V6  [C_0402]  93.42 35.26 90 bottom
PC2021  0.1U_0402_25V6  [C_0402]  94.32 35.27 90 top
PC2200  1U_0402_25V6K  [C_0402]  56.69 62.69 180 bottom
PC2201  1000P_0402_50V7K  [C_0402]  55.66 60.6 270 top
PC2202  0.1U_0402_25V6  [C_0402]  58.2 62.06 90 bottom
PC2203  2200P_0402_50V7K  [C_0402]  58.14 61.12 270 bottom
PC2204  10U_0603_25V6M  [C_0603]  56.87 60.72 270 top
PC2205  10U_0603_25V6M  [C_0603]  56.87 60.98 270 bottom
PC2206  0.22U_0603_16V7K  [C_0603]  55.66 56.03 0 top
PC2207  2200P_0402_50V7K  [C_0402]  63.47 56.72 0 top
PC2208  2.2U_0603_16V6K  [C_0603]  59.66 51.71 90 top
PC2215  22U_0603_6.3V6M  [C_0603]  126.65 75.01 180 top
PC2216  22U_0603_6.3V6M  [C_0603]  138.08 65.74 0 top
PC2217  22U_0603_6.3V6M  [C_0603]  125.38 69.42 180 top
PC2218  22U_0603_6.3V6M  [C_0603]  126.65 64.85 180 top
PC2219  22U_0603_6.3V6M  [C_0603]  124.24 75.01 180 top
PC2222  22U_0603_6.3V6M  [C_0603]  138.08 55.58 0 top
PC2223  1U_0201_6.3V6M  [C_0201]  128.11 64.94 90 top
PC2224  1U_0201_6.3V6M  [C_0201]  128.11 66.8 270 top
PC2225  1U_0201_6.3V6M  [C_0201]  128.11 67.48 90 top
PC2227  1U_0201_6.3V6M  [C_0201]  122.06 77.04 180 top
PC2229  10U_0402_6.3V6M  [C_0402]  127.23 67.32 90 top
PC2230  22U_0603_6.3V6M  [C_0603]  138.08 67.01 0 top
PC2231  1U_0201_6.3V6M  [C_0201]  128.11 61.72 270 top
PC2232  22U_0603_6.3V6M  [C_0603]  138.08 59.39 0 top
PC2235  1U_0201_6.3V6M  [C_0201]  122.74 77.04 0 top
PC2236  1U_0201_6.3V6M  [C_0201]  128.11 70.15 90 top
PC2237  22U_0603_6.3V6M  [C_0603]  138.08 58.12 0 top
PC2238  22U_0603_6.3V6M  [C_0603]  138.08 68.28 0 top
PC2241  1U_0201_6.3V6M  [C_0201]  128.11 69.34 270 top
PC2243  22U_0603_6.3V6M  [C_0603]  127.73 75.58 90 top
PC2249  22U_0603_6.3V6M  [C_0603]  124.24 73.74 180 top
PC2252  1U_0201_6.3V6M  [C_0201]  128.11 64.26 270 top
PC2253  1U_0201_6.3V6M  [C_0201]  124.6 77.04 180 top
PC2256  10U_0402_6.3V6M  [C_0402]  126.16 66 180 top
PC2257  10U_0402_6.3V6M  [C_0402]  127.23 61.88 270 top
PC2258  22U_0603_6.3V6M  [C_0603]  138.08 64.47 0 top
PC2259  10U_0402_6.3V6M  [C_0402]  127.23 72.78 90 top
PC2260  10U_0402_6.3V6M  [C_0402]  126.08 72.78 90 top
PC2262  22U_0603_6.3V6M  [C_0603]  126.02 68.15 180 top
PC2263  10U_0402_6.3V6M  [C_0402]  121.84 75.52 180 top
PC2264  10U_0402_6.3V6M  [C_0402]  127.23 71.79 270 top
PC2266  1U_0201_6.3V6M  [C_0201]  128.11 72 270 top
PC2267  22U_0603_6.3V6M  [C_0603]  138.08 56.85 0 top
PC2268  330U_B2_2.5VM_R9M  [C_B2]  139.34 59.44 180 bottom
PC2270  330U_B2_2.5VM_R9M  [C_B2]  141.84 70.24 180 bottom
PC2272  1U_0201_6.3V6M  [C_0201]  128.11 72.69 90 top
PC2273  10U_0402_6.3V6M  [C_0402]  127.23 70.01 270 top
PC2275  10U_0402_6.3V6M  [C_0402]  124.99 76.28 0 top
PC2276  10U_0402_6.3V6M  [C_0402]  121.84 74.5 180 top
PC2280  1U_0201_6.3V6M  [C_0201]  125.41 77.04 0 top
PC2281  1U_0201_6.3V6M  [C_0201]  128.11 62.4 90 top
PC2283  22U_0603_6.3V6M  [C_0603]  138.08 61.93 0 top
PC2284  10U_0402_6.3V6M  [C_0402]  126.16 67.01 180 top
PC2285  22U_0603_6.3V6M  [C_0603]  138.08 63.2 0 top
PC2286  22U_0603_6.3V6M  [C_0603]  138.08 60.66 0 top
PC2291  10U_0402_6.3V6M  [C_0402]  126.41 63.71 180 top
PC2292  0.1U_0402_10V7K  [C_0402]  137.82 54.44 0 top
PC2293  0.1U_0402_10V7K  [C_0402]  137.82 53.3 0 top
PC2294  100P_0402_50V8J  [C_0402]  140.1 54.44 0 top
PC2295  100P_0402_50V8J  [C_0402]  140.1 53.3 0 top
PC2300  1U_0402_6.3V6K  [C_0402]  80.84 106.11 0 top
PC2301  22U_0603_6.3V6M  [C_0603]  78.86 107 180 top
PC2302  22P_0402_50V8J  [C_0402]  85.19 107.57 90 top
PC2303  22U_0603_6.3V6M  [C_0603]  84.59 105.89 270 top
PC2304  0.1U_0402_16V7K  [C_0402]  78.99 110.31 90 top
PC3000  10U_0402_6.3V6M  [C_0402]  81.25 70.36 90 top
PC3001  10U_0402_6.3V6M  [C_0402]  66.9 65.16 90 top
PC3002  10U_0402_6.3V6M  [C_0402]  70.96 71 90 bottom
PC3003  10U_0402_6.3V6M  [C_0402]  82.14 70.36 90 top
PC3004  10U_0402_6.3V6M  [C_0402]  70.41 68.79 180 bottom
PC3005  10U_0402_6.3V6M  [C_0402]  65.88 65.16 90 top
PC3006  10U_0402_6.3V6M  [C_0402]  71.04 69.93 180 bottom
PC3007  10U_0402_6.3V6M  [C_0402]  83.03 70.36 90 top
PC3008  10U_0402_6.3V6M  [C_0402]  64.74 65.23 90 top
PC3009  10U_0402_6.3V6M  [C_0402]  71.04 61.42 180 bottom
PC3010  10U_0402_6.3V6M  [C_0402]  83.92 70.36 90 top
PC3011  10U_0402_6.3V6M  [C_0402]  79.52 75.33 0 top
PC3012  1U_0201_6.3V6M  [C_0201]  79.28 70.91 90 top
PC3033  330U_B2_2.5VM_R9M  [C_B2]  66.37 66.44 0 bottom
PC3034  220U_D7_2VM_R6M  [C_EEFSS0D221R]  67.19 62.28 270 top
PC3035  47U_0603_6.3V6M  [C_0603]  79.54 68.15 0 top
PC3036  47U_0603_6.3V6M  [C_0603]  79.54 72.98 0 top
PC3037  47U_0603_6.3V6M  [C_0603]  80.17 70.44 90 top
PC3038  47U_0603_6.3V6M  [C_0603]  68.04 64.66 90 top
PC3039  47U_0603_6.3V6M  [C_0603]  95.86 45.74 0 top
PC3040  47U_0603_6.3V6M  [C_0603]  98.35 46.96 270 top
PC3041  47U_0603_6.3V6M  [C_0603]  92.91 73.34 0 top
PC3042  47U_0603_6.3V6M  [C_0603]  99.62 74.62 180 top
PC3043  47U_0603_6.3V6M  [C_0603]  87.77 73.25 0 top
PC3044  47U_0603_6.3V6M  [C_0603]  100.95 73.28 0 top
PC3045  47U_0603_6.3V6M  [C_0603]  95.49 74.62 0 top
PC3046  47U_0603_6.3V6M  [C_0603]  84.11 72.83 180 top
PC3047  47U_0603_6.3V6M  [C_0603]  86.7 72.5 180 top
PC3048  47U_0603_6.3V6M  [C_0603]  87.77 74.58 0 top
PC3049  47U_0603_6.3V6M  [C_0603]  92.94 63.26 0 top
PC3050  47U_0603_6.3V6M  [C_0603]  95.48 64.66 0 top
PC3051  47U_0603_6.3V6M  [C_0603]  95.48 66.06 0 top
PC3052  47U_0603_6.3V6M  [C_0603]  79.31 49.07 270 top
PC3053  47U_0603_6.3V6M  [C_0603]  95.86 49.61 0 top
PC3054  47U_0603_6.3V6M  [C_0603]  95.86 48.34 0 top
PC3055  47U_0603_6.3V6M  [C_0603]  95.86 47.01 0 top
PC3056  47U_0603_6.3V6M  [C_0603]  77.96 49.07 270 top
PC3057  47U_0603_6.3V6M  [C_0603]  95.86 50.88 0 top
PC3058  47U_0603_6.3V6M  [C_0603]  92.94 64.66 0 top
PC3059  47U_0603_6.3V6M  [C_0603]  100.94 64.66 0 top
PC3060  47U_0603_6.3V6M  [C_0603]  100.94 66.06 0 top
PC3061  47U_0603_6.3V6M  [C_0603]  99.6 64.66 180 top
PC3062  47U_0603_6.3V6M  [C_0603]  84.11 74.1 180 top
PC3088  330U_B2_2.5VM_R9M  [C_B2]  77.53 51.07 0 bottom
PC3089  330U_B2_2.5VM_R9M  [C_B2]  89.2 50.92 0 bottom
PC3090  330U_B2_2.5VM_R9M  [C_B2]  94.2 50.95 0 bottom
PC3091  330U_B2_2.5VM_R9M  [C_B2]  96.97 50.95 180 bottom
PC3094  220U_D7_2VM_R6M  [C_EEFSS0D221R]  87.02 48.54 0 top
PC3095  220U_D7_2VM_R6M  [C_EEFSS0D221R]  87.02 43.86 0 top
PC3096  220U_D7_2VM_R6M  [C_EEFSS0D221R]  82.6 47.17 270 top
PC3097  220U_D7_2VM_R6M  [C_EEFSS0D221R]  78.23 44.71 180 top
PC3120  47U_0603_6.3V6M  [C_0603]  95.48 67.46 0 top
PC3121  47U_0603_6.3V6M  [C_0603]  92.94 67.46 0 top
PC3122  47U_0603_6.3V6M  [C_0603]  91.55 64.7 180 top
PC3123  47U_0603_6.3V6M  [C_0603]  91.68 73.3 180 top
PC3124  47U_0603_6.3V6M  [C_0603]  99.6 66.06 180 top
PC3125  47U_0603_6.3V6M  [C_0603]  92.91 72 0 top
PC3126  47U_0603_6.3V6M  [C_0603]  99.62 73.28 180 top
PC3127  47U_0603_6.3V6M  [C_0603]  95.49 73.28 0 top
PC3128  1U_0201_6.3V6M  [C_0201]  84.26 76.31 0 top
PC3129  1U_0201_6.3V6M  [C_0201]  83.45 76.28 180 top
PC3130  1U_0201_6.3V6M  [C_0201]  84.26 75.67 0 top
PC3131  1U_0201_6.3V6M  [C_0201]  87 76.28 180 top
PC3132  1U_0201_6.3V6M  [C_0201]  98.5 60.85 180 top
PC3133  1U_0201_6.3V6M  [C_0201]  87 75.65 180 top
PC3134  1U_0201_6.3V6M  [C_0201]  84.26 75.04 0 top
PC3135  1U_0201_6.3V6M  [C_0201]  101.83 61.58 0 top
PC3136  1U_0201_6.3V6M  [C_0201]  92.96 60.92 0 top
PC3137  1U_0201_6.3V6M  [C_0201]  91.47 60.88 180 top
PC3138  1U_0201_6.3V6M  [C_0201]  90.31 75.65 180 top
PC3139  1U_0201_6.3V6M  [C_0201]  90.31 76.28 180 top
PC3140  1U_0201_6.3V6M  [C_0201]  91.37 76.28 0 top
PC3141  1U_0201_6.3V6M  [C_0201]  88.2 76.28 0 top
PC3142  1U_0201_6.3V6M  [C_0201]  96.07 60.92 0 top
PC3143  1U_0201_6.3V6M  [C_0201]  99.75 60.92 0 top
PC3144  1U_0201_6.3V6M  [C_0201]  94.94 61.55 180 top
PC3145  1U_0201_6.3V6M  [C_0201]  91.37 75.65 0 top
PC3146  1U_0201_6.3V6M  [C_0201]  88.2 75.65 0 top
PC3147  1U_0201_6.3V6M  [C_0201]  94.94 60.92 180 top
PC3148  1U_0201_6.3V6M  [C_0201]  92.96 62.19 0 top
PC3149  1U_0201_6.3V6M  [C_0201]  101.86 62.17 0 top
PC3150  1U_0201_6.3V6M  [C_0201]  92.64 76.28 0 top
PC3151  1U_0201_6.3V6M  [C_0201]  94.62 76.28 180 top
PC3152  1U_0201_6.3V6M  [C_0201]  102.68 76.27 180 top
PC3153  1U_0201_6.3V6M  [C_0201]  100.85 75.63 0 top
PC3154  1U_0201_6.3V6M  [C_0201]  92.96 61.55 0 top
PC3155  1U_0201_6.3V6M  [C_0201]  94.94 62.19 180 top
PC3156  1U_0201_6.3V6M  [C_0201]  98.5 61.49 180 top
PC3157  1U_0201_6.3V6M  [C_0201]  83.45 75.65 180 top
PC3158  1U_0201_6.3V6M  [C_0201]  92.64 75.65 0 top
PC3159  1U_0201_6.3V6M  [C_0201]  94.62 75.65 180 top
PC3160  1U_0201_6.3V6M  [C_0201]  96.07 61.55 0 top
PC3161  1U_0201_6.3V6M  [C_0201]  100.34 61.55 180 top
PC3162  1U_0201_6.3V6M  [C_0201]  101.85 60.92 0 top
PC3163  1U_0201_6.3V6M  [C_0201]  102.68 75.63 180 top
PC3164  1U_0201_6.3V6M  [C_0201]  97.29 76.28 180 top
PC3165  1U_0201_6.3V6M  [C_0201]  89.29 62.95 180 top
PC3166  1U_0201_6.3V6M  [C_0201]  98.5 62.12 180 top
PC3167  1U_0201_6.3V6M  [C_0201]  96.07 62.19 0 top
PC3168  1U_0201_6.3V6M  [C_0201]  91.47 61.51 180 top
PC3169  1U_0201_6.3V6M  [C_0201]  95.31 75.65 0 top
PC3170  1U_0201_6.3V6M  [C_0201]  98.36 75.65 0 top
PC3171  1U_0201_6.3V6M  [C_0201]  97.29 75.65 180 top
PC3172  1U_0201_6.3V6M  [C_0201]  98.36 76.28 0 top
PC3173  1U_0201_6.3V6M  [C_0201]  95.31 76.28 0 top
PC3174  1U_0201_6.3V6M  [C_0201]  91.47 62.15 180 top
PC3175  1U_0201_6.3V6M  [C_0201]  83.45 75.01 180 top
PC3176  1U_0201_6.3V6M  [C_0201]  100.2 76.27 180 top
PC3177  1U_0201_6.3V6M  [C_0201]  100.21 75.66 180 top
PC3178  1U_0201_6.3V6M  [C_0201]  89.29 63.58 180 top
PC3179  1U_0201_6.3V6M  [C_0201]  100.85 76.27 0 top
PC3180  1U_0201_6.3V6M  [C_0201]  100.34 62.19 180 top
PC3192  220U_D7_2VM_R6M  [C_EEFSS0D221R]  59.98 67.15 180 top
PC3193  330U_B2_2.5VM_R9M  [C_B2]  69.44 64.62 270 bottom
PC3194  330U_B2_2.5VM_R9M  [C_B2]  66.37 63.2 0 bottom
PC3195  47U_0603_6.3V6M  [C_0603]  70.96 62.63 180 bottom
PC3196  47U_0603_6.3V6M  [C_0603]  91.67 71.96 180 top
PC3197  47U_0603_6.3V6M  [C_0603]  99.62 71.95 180 top
PC3198  47U_0603_6.3V6M  [C_0603]  99.6 67.46 180 top
PC3199  47U_0603_6.3V6M  [C_0603]  91.51 67.4 180 top
PC3200  47U_0603_6.3V6M  [C_0603]  92.88 74.61 0 top
PC3201  47U_0603_6.3V6M  [C_0603]  95.49 71.95 0 top
PC3202  47U_0603_6.3V6M  [C_0603]  91.7 74.61 180 top
PC3203  47U_0603_6.3V6M  [C_0603]  100.95 71.95 0 top
PC3204  47U_0603_6.3V6M  [C_0603]  99.6 63.32 180 top
PC3205  47U_0603_6.3V6M  [C_0603]  100.94 63.32 0 top
PC3206  47U_0603_6.3V6M  [C_0603]  83.22 69.11 270 top
PC3207  47U_0603_6.3V6M  [C_0603]  79.54 74.25 0 top
PC3208  47U_0603_6.3V6M  [C_0603]  82.01 69.11 270 top
PC3209  47U_0603_6.3V6M  [C_0603]  79.54 76.41 0 top
PC3210  47U_0603_6.3V6M  [C_0603]  92.91 66.08 0 top
PC3211  47U_0603_6.3V6M  [C_0603]  103.52 73.76 0 top
PC3212  47U_0603_6.3V6M  [C_0603]  91.51 66.08 180 top
PC3213  47U_0603_6.3V6M  [C_0603]  100.94 67.46 0 top
PC3214  47U_0603_6.3V6M  [C_0603]  95.53 63.28 0 top
PC3215  47U_0603_6.3V6M  [C_0603]  100.91 74.62 0 top
PC3216  47U_0603_6.3V6M  [C_0603]  87.79 71.94 0 top
PC3217  47U_0603_6.3V6M  [C_0603]  91.54 63.32 180 top
PC3218  10U_0402_6.3V6M  [C_0402]  87.78 77.88 90 top
PC3219  10U_0402_6.3V6M  [C_0402]  86.81 77.86 90 top
PC3220  10U_0402_6.3V6M  [C_0402]  85.84 77.84 90 top
PC3221  10U_0402_6.3V6M  [C_0402]  84.85 77.86 90 top
PC3222  10U_0402_6.3V6M  [C_0402]  83.85 77.81 90 top
PC3223  10U_0402_6.3V6M  [C_0402]  103.36 68.73 180 top
PC3224  10U_0402_6.3V6M  [C_0402]  100.61 68.73 0 top
PC3225  10U_0402_6.3V6M  [C_0402]  99.07 68.75 180 top
PC3226  10U_0402_6.3V6M  [C_0402]  96.14 68.69 0 top
PC3227  10U_0402_6.3V6M  [C_0402]  86.6 73.62 180 top
PC3228  10U_0402_6.3V6M  [C_0402]  95.17 68.73 180 top
PC3229  10U_0402_6.3V6M  [C_0402]  92.41 68.75 0 top
PC3230  10U_0402_6.3V6M  [C_0402]  91.44 68.74 180 top
PC3231  10U_0402_6.3V6M  [C_0402]  88.61 68.79 0 top
PC3232  10U_0402_6.3V6M  [C_0402]  103.34 69.75 180 top
PC3233  10U_0402_6.3V6M  [C_0402]  100.61 69.74 0 top
PC3234  10U_0402_6.3V6M  [C_0402]  99.06 69.77 180 top
PC3235  10U_0402_6.3V6M  [C_0402]  96.17 69.74 0 top
PC3236  10U_0402_6.3V6M  [C_0402]  86.59 74.64 180 top
PC3237  10U_0402_6.3V6M  [C_0402]  95.14 69.7 180 top
PC3238  10U_0402_6.3V6M  [C_0402]  92.39 69.73 0 top
PC3239  10U_0402_6.3V6M  [C_0402]  91.44 69.72 180 top
PC3240  10U_0402_6.3V6M  [C_0402]  88.62 69.78 0 top
PC3241  10U_0402_6.3V6M  [C_0402]  103.34 70.78 180 top
PC3242  10U_0402_6.3V6M  [C_0402]  100.62 70.77 0 top
PC3243  10U_0402_6.3V6M  [C_0402]  99.09 70.78 180 top
PC3244  10U_0402_6.3V6M  [C_0402]  96.14 70.76 0 top
PC3245  10U_0402_6.3V6M  [C_0402]  87.42 69.65 270 top
PC3246  10U_0402_6.3V6M  [C_0402]  95.12 70.72 180 top
PC3247  10U_0402_6.3V6M  [C_0402]  92.38 70.73 0 top
PC3248  10U_0402_6.3V6M  [C_0402]  91.39 70.72 180 top
PC3249  10U_0402_6.3V6M  [C_0402]  88.61 70.77 0 top
PC3250  10U_0402_6.3V6M  [C_0402]  103.56 75 0 top
PC3251  10U_0402_6.3V6M  [C_0402]  103.53 75.95 0 top
PC3252  10U_0402_6.3V6M  [C_0402]  103.49 76.9 0 top
PC3253  10U_0402_6.3V6M  [C_0402]  89.2 61.99 0 top
PC3254  10U_0402_6.3V6M  [C_0402]  89.2 61.07 0 top
PC3255  10U_0402_6.3V6M  [C_0402]  86.15 71.37 180 top
PC3256  10U_0402_6.3V6M  [C_0402]  86.19 70.4 180 top
PC3257  1U_0402_6.3V7K  [C_0402]  113.51 37.58 90 top
PC3258  1U_0402_6.3V7K  [C_0402]  120.7 37.63 90 top
PC3259  1U_0402_6.3V7K  [C_0402]  128.03 39.05 90 top
PC3260  1U_0402_6.3V7K  [C_0402]  105.83 38.45 90 top
PC3261  0.1U_0402_16V7K  [C_0402]  69.34 46.76 270 top
PC3262  22U_0603_6.3V6M  [C_0603]  64.54 49.77 270 top
PC3264  22P_0201_25V8  [C_0201]  69.22 51.41 180 top
PC3265  47U_0603_6.3V6M  [C_0603]  70.6 50.09 270 top
PC3266  680P_0402_50V7K  [C_0402]  64.69 52.67 0 bottom
PC3269  2.2U_0402_6.3V6M  [C_0402]  151.77 87.95 270 bottom
PC3270  680P_0402_50V7K  [C_0402]  152.01 85.07 90 bottom
PC3272  0.1U_0201_10V6K  [C_0201]  145.67 87.35 0 bottom
PC3273  10U_0603_25V6M  [C_0603]  147.09 94.12 0 bottom
PC3274  0.1U_0201_6.3V6K  [C_0201]  151.53 92.28 0 bottom
PC3276  10U_0603_25V6M  [C_0603]  145.59 91.24 270 bottom
PC3277  2200P_0402_50V7K  [C_0402]  147.24 93.08 0 bottom
PC3278  1U_0402_6.3V6K  [C_0402]  151.68 88.84 90 bottom
PC3282  47U_0603_6.3V6M  [C_0603]  141.34 80.55 270 bottom
PC3283  47U_0603_6.3V6M  [C_0603]  147.17 79.33 270 bottom
PC3284  47U_0603_6.3V6M  [C_0603]  141.37 81.71 90 bottom
PC3285  330P_0201_50V7K  [C_0201]  150.91 89.17 0 top
PC3287  0.01U_0201_10V7K  [C_0201]  66.48 51.55 90 top
PC3288  220U_D7_2VM_R6M  [C_EEFSS0D221R]  120.85 79.94 0 top
PC3289  0.1U_0201_10V6K  [C_0201]  47.84 41.03 90 top
PD102  -  [RB520SM-30T2R_EMD2-2]  32.82 106.64 180 top
PD103  -  [RB520SM-30T2R_EMD2-2]  30.55 92.16 0 top
PD104  -  [TVNST52302AB0_SOT523-3]  126.84 14.94 180 top
PD105  -  [TVNST52302AB0_SOT523-3]  124.81 14.94 180 top
PD106  -  [BAT54CW_SOT323-3]  41.88 105.48 90 bottom
PD107  -  [BAT54CW_SOT323-3]  41.88 102.88 90 bottom
PD108  -  [BAT54CW_SOT323-3]  38.58 105.48 90 bottom
PD109  -  [BAT54CW_SOT323-3]  38.58 102.88 90 bottom
PD304  -  [RB520SM-30T2R_EMD2-2]  48.33 66.63 0 bottom
PD305  -  [RB520SM-30T2R_EMD2-2]  48.33 67.84 0 bottom
PD306  -  [RB520SM-30T2R_EMD2-2]  48.33 65.42 0 bottom
PD307  -  [RB520SM-30T2R_EMD2-2]  48.33 64.22 0 bottom
PD308  -  [RB520SM-30T2R_EMD2-2]  47.99 63 180 bottom
PD500  -  [RB520SM-30T2R_EMD2-2]  51.79 106.88 270 top
PD501  -  [RB520SM-30T2R_EMD2-2]  166.29 11.07 180 bottom
PD505  -  [BAT54CW_SOT323-3]  145.31 5.53 270 bottom
PD506  -  [RB520SM-30T2R_EMD2-2]  52.89 102.81 180 top
PD508  -  [RB520SM-30T2R_EMD2-2]  52.89 101.59 180 top
PD509  -  [RB520SM-30T2R_EMD2-2]  52.89 104.06 180 top
PD510  SMF4L22A SOD123FL-2  [SMF22A-SOD123FL-2-S]  4.43 62.12 0 bottom
PD800  RB751S40T1G_SOD523-2  [RB520SM-30T2R_EMD2-2]  78.01 95.85 90 top
PD1000  RB751S40T1G_SOD523-2  [RB520SM-30T2R_EMD2-2]  101.58 22.73 0 top
PD2300  RB751S40T1G_SOD523-2  [RB520SM-30T2R_EMD2-2]  76.87 109.16 90 top
PH1800  100K_0402_1%_B25/50 4250K  [R_0402]  91.14 48.79 0 bottom
PH1801  100K_0402_1%_B25/50 4250K  [R_0402]  69.3 55.52 0 bottom
PJP501  -  [JUMP_43X39]  144.56 5.3 270 top
PJP502  -  [JUMP_43X39]  136.5 2.81 270 top
PJP600  PAD-OPEN 4X4M  [JUMP_43X118]  16.79 27.64 0 bottom
PJP601  PAD-OPEN 4X4M  [JUMP_43X118]  53.02 87.37 270 bottom
PJP602  PAD-OPEN 4X4M  [JUMP_43X118]  111.41 24.7 270 bottom
PJP603  PAD-OPEN 4X4M  [JUMP_43X118]  74.62 102.55 270 top
PJP700  -  [JUMP_43X118]  13.45 35.49 0 bottom
PJP800  -  [JUMP_43X118]  90.04 100.41 0 bottom
PJP801  -  [JUMP_43X39]  75.17 92.47 180 bottom
PJP900  -  [JUMP_43X39]  24.09 25.36 0 top
PJP1000  -  [JUMP_43X118]  102.67 40.6 0 top
PJP1001  -  [JUMP_43X39]  97.05 29.01 270 top
PJP1402  PAD-OPEN1X1M  [JUMP_43X39]  41.25 7.05 90 bottom
PJP1500  -  [JUMP_43X79]  64.56 78.14 90 top
PJP1701  -  [JUMP_43X79]  72.39 49.39 0 top
PJP1702  -  [JUMP_43X118]  139.15 81.33 180 bottom
PL100  HCB2012KF-121T50_0805  [TAI-T_HCB2012KF-121T50_2P]  14.87 73.55 270 bottom
PL101  HCB2012KF-121T50_0805  [TAI-T_HCB2012KF-121T50_2P]  13.04 73.45 270 bottom
PL102  HCB2012KF-121T50_0805  [TAI-T_HCB2012KF-121T50_2P]  20.16 100.27 270 bottom
PL103  HCB2012KF-121T50_0805  [TAI-T_HCB2012KF-121T50_2P]  18.36 100.26 270 bottom
PL104  HCB2012KF-121T50_0805  [TAI-T_HCB2012KF-121T50_2P]  138.08 3.7 180 bottom
PL105  HCB2012KF-121T50_0805  [TAI-T_HCB2012KF-121T50_2P]  138.08 1.91 180 bottom
PL106  HCB2012KF-121T50_0805  [TAI-T_HCB2012KF-121T50_2P]  137.37 5.49 180 bottom
PL500  1.5UH_MMD-05CZ-1R5M-X2L_6A_20%  [MAG_MMD-05CZ-1R5M-X2L_2P]  151.86 4.51 90 bottom
PL501  1UH_MMD-10CZN1R0M-R1L_20A_20%  [MAG_MMD-10CZN1R0M-R1L_2P]  152.3 23.26 180 bottom
PL502  HCB1608KF-121T30_0603  [TAI-T_HCB1608KF-121T3_L0603_2P]  148.54 8.5 270 bottom
PL600  HCB2012KF-121T50_0805  [TAI-T_HCB2012KF-121T50_2P]  8.62 18.12 0 bottom
PL601  1UH_MMD-05CZ-1R0M-M7L_7A_20%  [MAGLA_MMD-05CZ-1R0M-M7L_2P]  11.02 26.86 90 bottom
PL602  HCB2012KF-121T50_0805  [TAI-T_HCB2012KF-121T50_2P]  57.72 74.39 90 bottom
PL603  1UH_MLD-06CZH1R0M-N1L_11.3A_20%  [MAG_MLD-06CZH1R0M-N1L_2P]  59.01 84.71 90 bottom
PL604  HCB2012KF-121T50_0805  [TAI-T_HCB2012KF-121T50_2P]  132.04 21.46 180 bottom
PL605  1UH_MLD-06CZH1R0M-N1L_11.3A_20%  [MAG_MLD-06CZH1R0M-N1L_2P]  121.7 25.42 180 bottom
